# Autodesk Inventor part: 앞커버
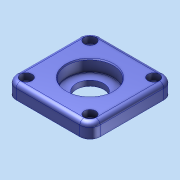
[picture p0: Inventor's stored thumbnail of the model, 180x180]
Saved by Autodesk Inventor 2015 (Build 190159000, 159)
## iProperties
Created: 2026-02
Part Number: 앞커버
Material: 일반
Document SubType Name: Modeling
Designer: Administrator
Density: 1 g/cm^3
Appearance: 기본값
Author: Administrator
Author: jhkim
Creation Date: 2026-01-30
Sending System: Autodesk Inventor 2026
Preprocessor: ST-DEVELOPER v20.1
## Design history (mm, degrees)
node "앞커버1"
node "솔리드1"
node "기준1"
